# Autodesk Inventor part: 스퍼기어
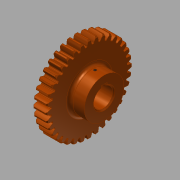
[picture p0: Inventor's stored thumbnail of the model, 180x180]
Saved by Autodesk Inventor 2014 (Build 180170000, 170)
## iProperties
Created: 2019-01
Part Number: 스퍼기어
Material: 알루미늄 6061
Document SubType Name: Modeling
Designer: mduedu
Density: 1 g/cm^3
Appearance: 매끄러움 - 연한 주황색
Author: mduedu
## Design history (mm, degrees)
sketch "스케치1"
  geometry: C1 r 33.5 at (0, 0); 1 further point
  constraints: 1 centre point, 1 coincident
  dimensions: "d0" = 67 diameter of C1
extrude "돌출1" new body sketch "스케치1" stored distance "d2" = 12; taper "d3" = 0 deg
sketch "스케치2" dims "d4" = 72
  geometry: L1 (0, 0)-(-38, 0); L2 (0, 0)-(0, 38); L3 (-0.57, 0)-(-0.57, 37.996); L4 (-1.57, 0)-(-1.57, 37.968); L5 (-2.07, 0)-(-2.07, 37.944); C1 r 33.5 at (0, 0); A1 r 38 centre (0, 0) between (-38, 0) and (0, 38); A2 r 9.246 centre (7.162, 32.926) between (-0.57, 37.996) and (-2.07, 33.436); A3 r 9.246 centre (-7.162, 32.926) between (2.07, 33.436) and (0.57, 37.996); A4 r 33.5 centre (0, 0) between (2.07, 33.436) and (-2.07, 33.436); A5 r 38 centre (0, 0) between (0.57, 37.996) and (-0.57, 37.996); 3 further points
  constraints: 14 point on circle, 10 end point, 6 centre point, 5 coincident, 5 point on line, 3 symmetric about line, 2 parallel, 2 perpendicular, 1 horizontal, 7 other
  dimensions: "d6" = 76 diameter of A1; "d7" = 0.5 distance between parallel lines of L4 L5; "d8" = 1 distance between parallel lines of L3 L4; "d9" = 1.57 distance between parallel lines of L2 L4
extrude "돌출2" join sketch "스케치2" stored distance "d10" = 0; taper "d11" = 0 deg
chamfer "모따기1" distance "d12" = 1; stored, may be unused: second distance "d13" = 2, angle "d14" = 45 deg
fillet "모깎기1" dims "d15" = 0.5
sketch "스케치3"
  geometry: C1 r 17.5 at (0, 0); 1 further point
  constraints: 1 centre point, 1 coincident
  dimensions: "d19" = 35 diameter of C1
extrude "돌출3" join sketch "스케치3" distance "d20" = 13; taper "d21" = 0 deg
sketch "스케치4"
  geometry: L1 (-2.5, 8.124)-(2.5, 8.124); L2 (2.5, 8.124)-(2.5, 10.8); L3 (2.5, 10.8)-(-2.5, 10.8); L4 (-2.5, 10.8)-(-2.5, 8.124); A1 r 8.5 centre (0, 0) between (-2.5, 8.124) and (2.5, 8.124); 1 further point
  constraints: 8 end point, 2 parallel, 2 point on circle, 1 centre point, 1 coincident, 1 horizontal, 1 perpendicular
  dimensions: "d22" = 17 diameter of A1; "d23" = 5 distance of L2.end L3.end; "d24" = 19.3 dimension on A1 L3
extrude "돌출4" cut sketch "스케치4" stored distance "d25" = 13; taper "d26" = 0 deg
sketch "스케치5"
  geometry: C1 r 15 at (0, 0); C2 r 27.5 at (0, 0); 1 further point
  constraints: 2 centre point, 2 coincident
  dimensions: "d33" = 30 diameter of C1; "d34" = 55 diameter of C2
extrude "돌출5" cut sketch "스케치5" distance "d30" = 6; taper "d31" = 0 deg
fillet "모깎기2" dims "d32" = 3
node "작업 평면1"
sketch "스케치6"
  geometry: L1 (17.5, 13)-(-17.5, 13) reference; 2 further points
  constraints: 1 vertical alignment
  dimensions: "d35" = 8 distance from line of point (0, 5) L1
hole "구멍1" sketch "스케치6" at (0, 5) diameter "d36" = 2.459; stored, may be unused: countersink angle "d40" = 90 deg, drill point angle "d42" = 118 deg; dims "d37" = 6, "d38" = 4, "d39" = 2, "d41" = 8
fillet "모깎기3" dims "d43" = 3
chamfer "모따기2" distance "d44" = 1; stored, may be unused: second distance "d45" = 2, angle "d46" = 45 deg
node "솔리드1"
pattern_circular "원형 패턴1" dims "d17" = 360 deg
